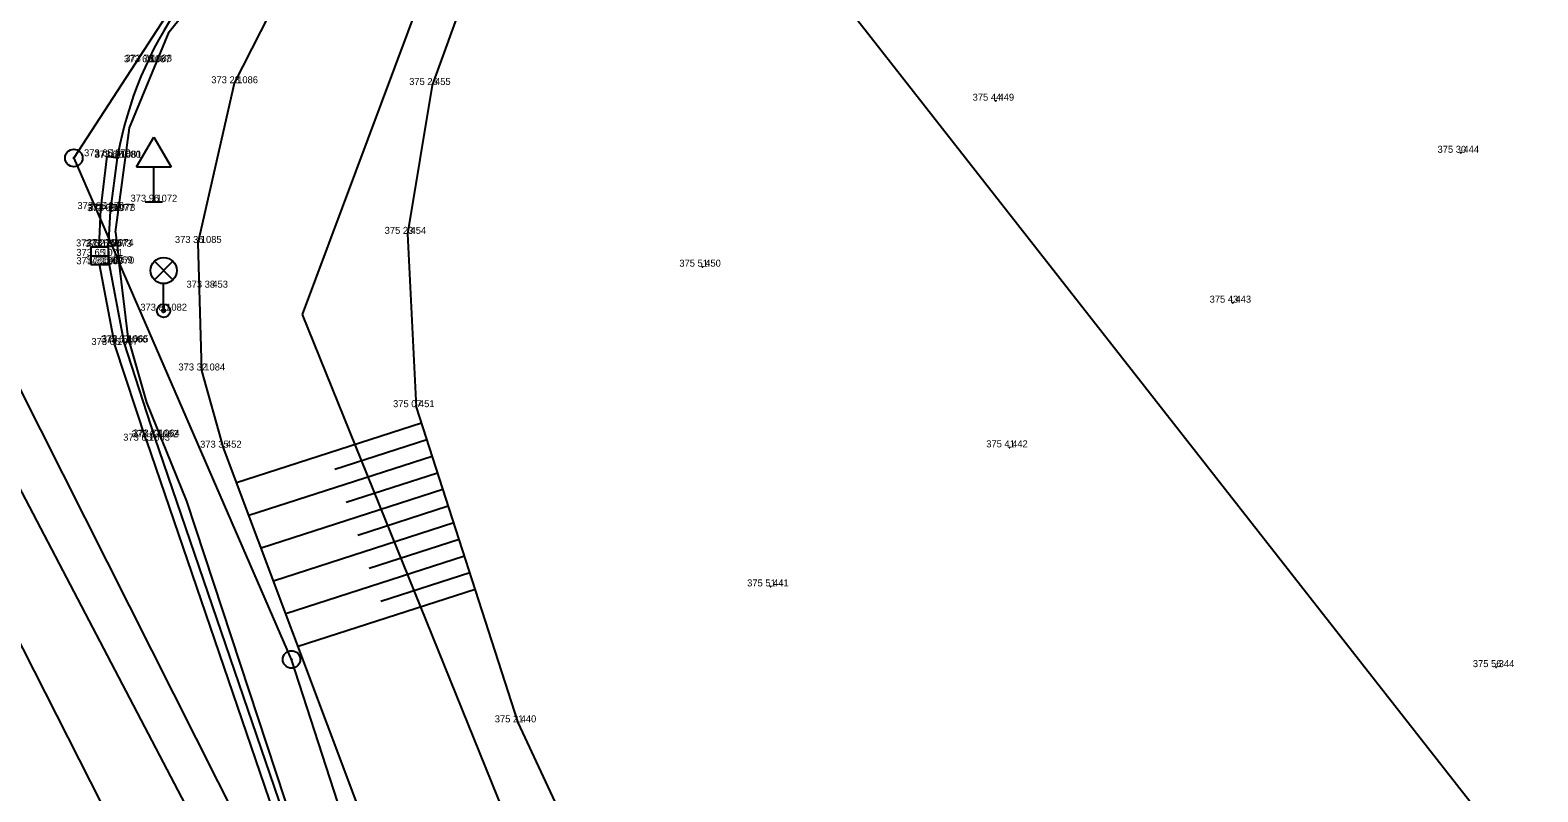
# Model space of a CAD drawing. Extents: x -601196 to -600262, y -1082523 to -1081922.
# Drawn here: x -600508.65 to -600465.52, y -1082233.43 to -1082211.63 of the extents above; entities that cross this region are included whole.
import ezdxf

# ---------------------------------------------------------------- set-up
doc = ezdxf.new("R2010")
doc.units = 0
for name, color, linetype in [('Vrstva 1', 7, 'Continuous'), ('Vrstva 10', 7, 'Continuous'), ('Vrstva 11', 7, 'Continuous'), ('Vrstva 14', 7, 'Continuous'), ('Vrstva 2', 7, 'Continuous'), ('Vrstva 20', 7, 'Continuous'), ('Vrstva 25', 7, 'Continuous'), ('Vrstva 27', 7, 'Continuous'), ('Vrstva 3', 7, 'Continuous'), ('Vrstva 33', 7, 'Continuous'), ('Vrstva 34', 7, 'Continuous'), ('Vrstva 47', 7, 'Continuous')]:
    doc.layers.add(name, color=color, linetype=linetype)

msp = doc.modelspace()

# ---------------------------------------------------------------- linework, layer by layer
at = {"layer": 'Vrstva 1'}
for p, q in [((-600505.3, -1082212.55), (-600505.3, -1082212.55)), ((-600505.26, -1082212.53), (-600505.26, -1082212.53)), ((-600502.8, -1082213.15), (-600502.8, -1082213.15)), ((-600497.14, -1082213.2), (-600497.14, -1082213.2)), ((-600481.02, -1082213.65), (-600481.02, -1082213.65)), ((-600506.44, -1082215.24), (-600506.44, -1082215.24)), ((-600506.15, -1082215.28), (-600506.15, -1082215.28)), ((-600506.13, -1082215.28), (-600506.13, -1082215.28)), ((-600467.72, -1082215.14), (-600467.72, -1082215.14)), ((-600505.11, -1082216.54), (-600505.11, -1082216.54)), ((-600506.63, -1082216.75), (-600506.63, -1082216.75)), ((-600506.35, -1082216.81), (-600506.35, -1082216.81)), ((-600506.31, -1082216.8), (-600506.31, -1082216.8)), ((-600497.84, -1082217.46), (-600497.84, -1082217.46)), ((-600506.67, -1082217.82), (-600506.67, -1082217.82)), ((-600506.41, -1082217.83), (-600506.41, -1082217.83)), ((-600506.36, -1082217.81), (-600506.36, -1082217.81)), ((-600503.84, -1082217.72), (-600503.84, -1082217.72)), ((-600506.66, -1082218.09), (-600506.66, -1082218.09)), ((-600506.66, -1082218.33), (-600506.66, -1082218.33)), ((-600506.39, -1082218.3), (-600506.39, -1082218.3)), ((-600506.34, -1082218.31), (-600506.34, -1082218.31)), ((-600489.41, -1082218.4), (-600489.41, -1082218.4)), ((-600503.51, -1082219), (-600503.51, -1082219)), ((-600504.83, -1082219.66), (-600504.83, -1082219.66)), ((-600474.24, -1082219.43), (-600474.24, -1082219.43)), ((-600505.96, -1082220.57), (-600505.96, -1082220.57)), ((-600505.93, -1082220.56), (-600505.93, -1082220.56)), ((-600506.23, -1082220.64), (-600506.23, -1082220.64)), ((-600503.74, -1082221.37), (-600503.74, -1082221.37)), ((-600497.6, -1082222.42), (-600497.6, -1082222.42)), ((-600505.32, -1082223.38), (-600505.32, -1082223.38)), ((-600505.08, -1082223.28), (-600505.08, -1082223.28)), ((-600505.04, -1082223.26), (-600505.04, -1082223.26)), ((-600503.12, -1082223.58), (-600503.12, -1082223.58)), ((-600480.63, -1082223.57), (-600480.63, -1082223.57)), ((-600487.47, -1082227.55), (-600487.47, -1082227.55)), ((-600466.71, -1082229.86), (-600466.71, -1082229.86)), ((-600494.69, -1082231.44), (-600494.69, -1082231.44))]:
    msp.add_line(p, q, dxfattribs=at)
at = {"layer": 'Vrstva 10'}
for p, q in [((-600506.35, -1082216.81), (-600506.15, -1082215.28)), ((-600506.41, -1082217.83), (-600506.35, -1082216.81)), ((-600506.39, -1082218.3), (-600506.41, -1082217.83)), ((-600505.96, -1082220.57), (-600506.39, -1082218.3)), ((-600505.08, -1082223.28), (-600505.96, -1082220.57)), ((-600500.2, -1082237.57), (-600505.08, -1082223.28))]:
    msp.add_line(p, q, dxfattribs=at)
msp.add_lwpolyline([(-600503.63, -1082209.99), (-600503.82, -1082210.212), (-600504.004, -1082210.439), (-600504.181, -1082210.671), (-600504.352, -1082210.908), (-600504.517, -1082211.15), (-600504.675, -1082211.396), (-600504.826, -1082211.646), (-600504.97, -1082211.9), (-600505.108, -1082212.158), (-600505.238, -1082212.42), (-600505.362, -1082212.685), (-600505.478, -1082212.953), (-600505.586, -1082213.225), (-600505.687, -1082213.499), (-600505.781, -1082213.776), (-600505.867, -1082214.055), (-600505.946, -1082214.337), (-600506.016, -1082214.62), (-600506.08, -1082214.906), (-600506.135, -1082215.193), (-600506.15, -1082215.28)], dxfattribs=at)
at = {"layer": 'Vrstva 11'}
for p, q in [((-600506.63, -1082216.75), (-600506.44, -1082215.24)), ((-600506.44, -1082215.24), (-600506.15, -1082215.28)), ((-600506.67, -1082217.82), (-600506.63, -1082216.75)), ((-600506.41, -1082217.83), (-600506.67, -1082217.82)), ((-600506.66, -1082218.33), (-600506.39, -1082218.3)), ((-600506.23, -1082220.64), (-600506.66, -1082218.33)), ((-600505.32, -1082223.38), (-600506.23, -1082220.64)), ((-600505.32, -1082223.38), (-600500.43, -1082237.68))]:
    msp.add_line(p, q, dxfattribs=at)
at = {"layer": 'Vrstva 14'}
for p, q in [((-600497.14, -1082213.2), (-600494.82, -1082206.84)), ((-600502.8, -1082213.15), (-600501.54, -1082210.67)), ((-600503.84, -1082217.72), (-600502.8, -1082213.15)), ((-600497.84, -1082217.46), (-600497.14, -1082213.2)), ((-600497.6, -1082222.42), (-600497.84, -1082217.46)), ((-600503.74, -1082221.37), (-600503.84, -1082217.72)), ((-600503.12, -1082223.58), (-600503.74, -1082221.37)), ((-600494.69, -1082231.44), (-600497.6, -1082222.42)), ((-600499.15, -1082234.15), (-600503.12, -1082223.58)), ((-600490.28, -1082240.9), (-600494.69, -1082231.44))]:
    msp.add_line(p, q, dxfattribs=at)
at = {"layer": 'Vrstva 20'}
for p, q in [((-600505.27, -1082212.53), (-600505.25, -1082212.53)), ((-600505.26, -1082212.515), (-600505.26, -1082212.53)), ((-600505.26, -1082212.545), (-600505.26, -1082212.53)), ((-600481.03, -1082213.65), (-600481.01, -1082213.65)), ((-600481.02, -1082213.635), (-600481.02, -1082213.65)), ((-600481.02, -1082213.665), (-600481.02, -1082213.65)), ((-600506.14, -1082215.28), (-600506.12, -1082215.28)), ((-600506.13, -1082215.265), (-600506.13, -1082215.28)), ((-600506.13, -1082215.295), (-600506.13, -1082215.28)), ((-600467.73, -1082215.14), (-600467.71, -1082215.14)), ((-600467.72, -1082215.125), (-600467.72, -1082215.14)), ((-600467.72, -1082215.155), (-600467.72, -1082215.14)), ((-600506.32, -1082216.8), (-600506.3, -1082216.8)), ((-600506.31, -1082216.785), (-600506.31, -1082216.8)), ((-600506.31, -1082216.815), (-600506.31, -1082216.8)), ((-600506.37, -1082217.81), (-600506.35, -1082217.81)), ((-600506.36, -1082217.795), (-600506.36, -1082217.81)), ((-600506.36, -1082217.825), (-600506.36, -1082217.81)), ((-600506.35, -1082218.31), (-600506.33, -1082218.31)), ((-600506.34, -1082218.295), (-600506.34, -1082218.31)), ((-600506.34, -1082218.325), (-600506.34, -1082218.31)), ((-600489.42, -1082218.4), (-600489.4, -1082218.4)), ((-600489.41, -1082218.385), (-600489.41, -1082218.4)), ((-600489.41, -1082218.415), (-600489.41, -1082218.4)), ((-600474.25, -1082219.43), (-600474.23, -1082219.43)), ((-600474.24, -1082219.415), (-600474.24, -1082219.43)), ((-600474.24, -1082219.445), (-600474.24, -1082219.43)), ((-600505.94, -1082220.56), (-600505.92, -1082220.56)), ((-600505.93, -1082220.545), (-600505.93, -1082220.56)), ((-600505.93, -1082220.575), (-600505.93, -1082220.56)), ((-600505.05, -1082223.26), (-600505.03, -1082223.26)), ((-600505.04, -1082223.245), (-600505.04, -1082223.26)), ((-600505.04, -1082223.275), (-600505.04, -1082223.26)), ((-600480.64, -1082223.57), (-600480.62, -1082223.57)), ((-600480.63, -1082223.555), (-600480.63, -1082223.57)), ((-600480.63, -1082223.585), (-600480.63, -1082223.57)), ((-600487.48, -1082227.55), (-600487.46, -1082227.55)), ((-600487.47, -1082227.535), (-600487.47, -1082227.55)), ((-600487.47, -1082227.565), (-600487.47, -1082227.55)), ((-600466.72, -1082229.86), (-600466.7, -1082229.86)), ((-600466.71, -1082229.845), (-600466.71, -1082229.86)), ((-600466.71, -1082229.875), (-600466.71, -1082229.86))]:
    msp.add_line(p, q, dxfattribs=at)
at = {"layer": 'Vrstva 25'}
for p, q in [((-600497.453, -1082222.877), (-600502.743, -1082224.584)), ((-600497.299, -1082223.353), (-600499.933, -1082224.203)), ((-600497.146, -1082223.829), (-600502.391, -1082225.521)), ((-600496.992, -1082224.305), (-600499.604, -1082225.147)), ((-600496.839, -1082224.78), (-600502.039, -1082226.458)), ((-600496.685, -1082225.256), (-600499.274, -1082226.091)), ((-600496.532, -1082225.732), (-600501.687, -1082227.395)), ((-600496.378, -1082226.208), (-600498.945, -1082227.036)), ((-600496.225, -1082226.684), (-600501.335, -1082228.332)), ((-600496.071, -1082227.159), (-600498.615, -1082227.98)), ((-600495.918, -1082227.635), (-600500.983, -1082229.269))]:
    msp.add_line(p, q, dxfattribs=at)
at = {"layer": 'Vrstva 27'}
msp.add_line((-600506.91, -1082218.09), (-600506.41, -1082218.09), dxfattribs=at)
msp.add_lwpolyline([(-600506.91, -1082218.34), (-600506.41, -1082218.34), (-600506.41, -1082217.84), (-600506.91, -1082217.84)], close=True, dxfattribs=at)
at = {"layer": 'Vrstva 33'}
for p, q in [((-600505.095, -1082218.245), (-600504.565, -1082218.775)), ((-600505.095, -1082218.775), (-600504.565, -1082218.245)), ((-600504.83, -1082219.66), (-600504.83, -1082218.885))]:
    msp.add_line(p, q, dxfattribs=at)
for centre, radius in [((-600504.83, -1082218.51), 0.375), ((-600504.83, -1082219.66), 0.19), ((-600504.83, -1082219.66), 0.05)]:
    msp.add_circle(centre, radius, dxfattribs=at)
at = {"layer": 'Vrstva 34'}
for p, q in [((-600505.61, -1082215.54), (-600505.11, -1082214.69)), ((-600505.11, -1082214.69), (-600504.61, -1082215.54)), ((-600505.61, -1082215.54), (-600504.61, -1082215.54)), ((-600505.11, -1082216.54), (-600505.11, -1082215.54)), ((-600505.36, -1082216.54), (-600504.86, -1082216.54))]:
    msp.add_line(p, q, dxfattribs=at)
at = {"layer": 'Vrstva 47'}
for p, q in [((-600500.86, -1082219.77), (-600493.6, -1082200.35)), ((-600453.37, -1082251.69), (-600493.6, -1082200.35)), ((-600518.58, -1082202.79), (-600498.19, -1082243.23)), ((-600492.69, -1082255.78), (-600520.31, -1082203.04)), ((-600507.4, -1082215.29), (-600499.55, -1082203.2)), ((-600504.67, -1082211.68), (-600502.18, -1082208.54)), ((-600505.81, -1082214.43), (-600504.67, -1082211.68)), ((-600506.21, -1082217.41), (-600505.81, -1082214.43)), ((-600507.4, -1082215.29), (-600506.1, -1082218.28)), ((-600506.21, -1082217.41), (-600506.1, -1082218.28)), ((-600505.84, -1082220.42), (-600506.1, -1082218.28)), ((-600501.17, -1082229.64), (-600506.1, -1082218.28)), ((-600475.82, -1082281.64), (-600500.86, -1082219.77)), ((-600505.31, -1082222.29), (-600505.84, -1082220.42)), ((-600504.17, -1082225.11), (-600505.31, -1082222.29)), ((-600498.19, -1082243.23), (-600504.17, -1082225.11)), ((-600509.18, -1082228.7), (-600470.62, -1082304.61)), ((-600492.69, -1082255.78), (-600501.17, -1082229.64))]:
    msp.add_line(p, q, dxfattribs=at)
for centre, radius in [((-600507.4, -1082215.29), 0.25), ((-600507.4, -1082215.29), 0.005), ((-600501.17, -1082229.64), 0.25), ((-600501.17, -1082229.64), 0.005)]:
    msp.add_circle(centre, radius, dxfattribs=at)

# ---------------------------------------------------------------- texts
at = {"layer": 'Vrstva 2'}
for s, p in [(' 1087', (-600505.3, -1082212.55)), (' 1088', (-600505.26, -1082212.53)), (' 1086', (-600502.8, -1082213.15)), (' 455', (-600497.14, -1082213.2)), (' 449', (-600481.02, -1082213.65)), (' 444', (-600467.72, -1082215.14)), (' 1079', (-600506.44, -1082215.24)), (' 1080', (-600506.15, -1082215.28)), (' 1081', (-600506.13, -1082215.28)), (' 1076', (-600506.63, -1082216.75)), (' 1077', (-600506.35, -1082216.81)), (' 1078', (-600506.31, -1082216.8)), (' 1072', (-600505.11, -1082216.54)), (' 1085', (-600503.84, -1082217.72)), (' 454', (-600497.84, -1082217.46)), (' 1075', (-600506.67, -1082217.82)), (' 1071', (-600506.66, -1082218.09)), (' 1073', (-600506.41, -1082217.83)), (' 1074', (-600506.36, -1082217.81)), (' 1068', (-600506.66, -1082218.33)), (' 1069', (-600506.39, -1082218.3)), (' 1070', (-600506.34, -1082218.31)), (' 450', (-600489.41, -1082218.4)), (' 453', (-600503.51, -1082219)), (' 443', (-600474.24, -1082219.43)), (' 1082', (-600504.83, -1082219.66)), (' 1067', (-600506.23, -1082220.64)), (' 1066', (-600505.96, -1082220.57)), (' 1065', (-600505.93, -1082220.56)), (' 1084', (-600503.74, -1082221.37)), (' 451', (-600497.6, -1082222.42)), (' 1063', (-600505.32, -1082223.38)), (' 1062', (-600505.08, -1082223.28)), (' 1064', (-600505.04, -1082223.26)), (' 452', (-600503.12, -1082223.58)), (' 442', (-600480.63, -1082223.57)), (' 441', (-600487.47, -1082227.55)), (' 344', (-600466.71, -1082229.86)), (' 440', (-600494.69, -1082231.44))]:
    msp.add_text(s, height=0.2, dxfattribs=at).set_placement(p)
at = {"layer": 'Vrstva 3'}
for s, p in [('373 69 ', (-600505.966, -1082212.55)), ('373 78 ', (-600505.926, -1082212.53)), ('373 28 ', (-600503.466, -1082213.15)), ('375 26 ', (-600497.806, -1082213.2)), ('375 44 ', (-600481.686, -1082213.65)), ('375 30 ', (-600468.386, -1082215.14)), ('373 65 ', (-600507.106, -1082215.24)), ('373 67 ', (-600506.816, -1082215.28)), ('373 76 ', (-600506.796, -1082215.28)), ('373 65 ', (-600507.296, -1082216.75)), ('373 65 ', (-600507.016, -1082216.81)), ('373 76 ', (-600506.976, -1082216.8)), ('373 96 ', (-600505.776, -1082216.54)), ('373 36 ', (-600504.506, -1082217.72)), ('375 23 ', (-600498.506, -1082217.46)), ('373 62 ', (-600507.336, -1082217.82)), ('373 65 ', (-600507.326, -1082218.09)), ('373 63 ', (-600507.076, -1082217.83)), ('373 76 ', (-600507.026, -1082217.81)), ('373 64 ', (-600507.326, -1082218.33)), ('373 64 ', (-600507.056, -1082218.3)), ('373 77 ', (-600507.006, -1082218.31)), ('375 51 ', (-600490.076, -1082218.4)), ('373 38 ', (-600504.176, -1082219)), ('375 43 ', (-600474.906, -1082219.43)), ('373 80 ', (-600505.496, -1082219.66)), ('373 66 ', (-600506.896, -1082220.64)), ('373 67 ', (-600506.626, -1082220.57)), ('373 77 ', (-600506.596, -1082220.56)), ('373 32 ', (-600504.406, -1082221.37)), ('375 07 ', (-600498.266, -1082222.42)), ('373 65 ', (-600505.986, -1082223.38)), ('373 67 ', (-600505.746, -1082223.28)), ('373 77 ', (-600505.706, -1082223.26)), ('373 35 ', (-600503.786, -1082223.58)), ('375 41 ', (-600481.296, -1082223.57)), ('375 51 ', (-600488.136, -1082227.55)), ('375 56 ', (-600467.376, -1082229.86)), ('375 21 ', (-600495.356, -1082231.44))]:
    msp.add_text(s, height=0.2, dxfattribs=at).set_placement(p)

doc.saveas('drawing.dxf')
